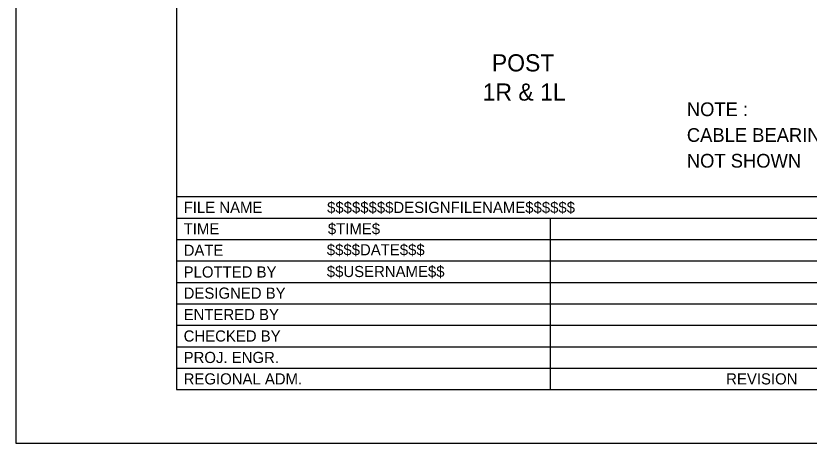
# Model space of a CAD drawing. Extents: x 1312564.2 to 1312581.5, y 1207298.4 to 1207352.6.
# Drawn here: x 1312564.478 to 1312569.104, y 1207312.821 to 1207315.314 of the extents above; entities that cross this region are included whole.
import ezdxf

# ---------------------------------------------------------------- set-up
doc = ezdxf.new("R2010")
doc.units = 0
for name, color, linetype in [('Level 1', 7, 'Continuous'), ('Level 15', 7, 'Continuous'), ('Level 2', 7, 'Continuous'), ('Level 20', 7, 'Continuous'), ('Level 36', 7, 'Continuous'), ('SH_GI_SheetTextInCells', 7, 'Continuous')]:
    doc.layers.add(name, color=color, linetype=linetype)

msp = doc.modelspace()

# ---------------------------------------------------------------- linework, layer by layer
at = {"layer": 'Level 1'}
for p, q in [((1312565.4155, 1207323.5084), (1312565.4155, 1207313.1334)), ((1312565.4155, 1207314.2593), (1312581.1655, 1207314.2593)), ((1312565.4155, 1207314.1342), (1312572.8721, 1207314.1342)), ((1312567.5945, 1207314.1342), (1312567.5945, 1207313.1334)), ((1312565.4155, 1207314.0091), (1312567.5976, 1207314.0091)), ((1312567.5976, 1207314.0091), (1312570.8621, 1207314.0091)), ((1312565.4155, 1207313.884), (1312567.5976, 1207313.884)), ((1312567.5976, 1207313.884), (1312570.8621, 1207313.884)), ((1312565.4155, 1207313.7589), (1312570.8621, 1207313.7589)), ((1312565.4155, 1207313.6338), (1312570.8621, 1207313.6338)), ((1312565.4155, 1207313.5087), (1312570.8621, 1207313.5087)), ((1312565.4155, 1207313.3836), (1312570.8621, 1207313.3836)), ((1312565.4155, 1207313.2585), (1312570.8621, 1207313.2585)), ((1312565.4155, 1207313.1334), (1312581.1655, 1207313.1334))]:
    msp.add_line(p, q, dxfattribs=at)
at = {"layer": 'Level 2'}
msp.add_lwpolyline([(1312564.478, 1207312.8209), (1312581.478, 1207312.8209), (1312581.478, 1207323.8209), (1312564.478, 1207323.8209)], close=True, dxfattribs=at)

# ---------------------------------------------------------------- texts
at = {"layer": 'Level 15'}
for s, p in [('POST ', (1312567.2537, 1207314.9901)), ('1R & 1L', (1312567.2002, 1207314.8198))]:
    msp.add_text(s, height=0.10015, dxfattribs=at).set_placement(p)
at = {"layer": 'Level 20'}
for s, height, p in [('NOTE : ', 0.08012, (1312568.391, 1207314.7292)), ('CABLE BEARING PLATE ', 0.080117, (1312568.391, 1207314.579)), ('NOT SHOWN ', 0.08012, (1312568.391, 1207314.4287))]:
    msp.add_text(s, height=height, dxfattribs=at).set_placement(p)
at = {"layer": 'Level 36'}
for s, height, p in [('$$$$$$$$DESIGNFILENAME$$$$$$', 0.065052, (1312566.2929, 1207314.1642)), ('$TIME$', 0.06505, (1312566.2975, 1207314.0393)), ('$$$$DATE$$$', 0.065052, (1312566.2914, 1207313.9169)), ('$$USERNAME$$', 0.065052, (1312566.2914, 1207313.7901))]:
    msp.add_text(s, height=height, dxfattribs=at).set_placement(p)
at = {"layer": 'SH_GI_SheetTextInCells'}
for s, height, p in [('FILE NAME', 0.06505, (1312565.4565, 1207314.1642)), ('TIME', 0.06505, (1312565.4565, 1207314.0391)), ('DATE', 0.06505, (1312565.4565, 1207313.914)), ('PLOTTED BY', 0.06505, (1312565.4565, 1207313.7872)), ('DESIGNED BY', 0.065052, (1312565.4565, 1207313.6638)), ('ENTERED BY', 0.06505, (1312565.4565, 1207313.5387)), ('CHECKED BY', 0.06505, (1312565.4565, 1207313.4136)), ('PROJ. ENGR.', 0.065052, (1312565.4565, 1207313.2885)), ('REGIONAL ADM.', 0.065052, (1312565.4565, 1207313.1634)), ('REVISION', 0.06505, (1312568.6203, 1207313.1634))]:
    msp.add_text(s, height=height, dxfattribs=at).set_placement(p)

doc.saveas('drawing.dxf')
